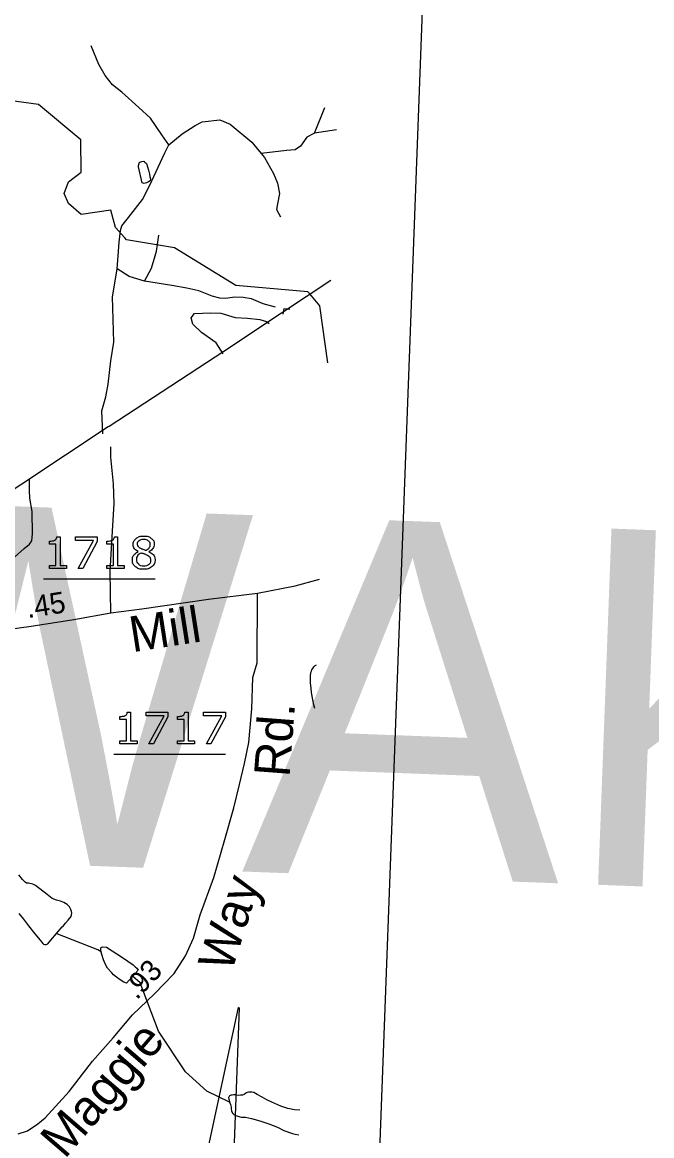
# Model space of a CAD drawing. Extents: x 2169602 to 2449496, y 721995 to 810662.
# Drawn here: x 2170523.6 to 2170611.8, y 724801.1 to 724957.3 of the extents above; entities that cross this region are included whole.
import ezdxf

# ---------------------------------------------------------------- set-up
doc = ezdxf.new("R2010")
doc.units = 0
for name, color, linetype in [('Old_Level_1', 7, 'Continuous'), ('Prop North Arrow NAD83 for Plan Sheets CELL', 7, 'Continuous'), ('Sheet Data Field CELL', 7, 'Continuous')]:
    doc.layers.add(name, color=color, linetype=linetype)

msp = doc.modelspace()

# ---------------------------------------------------------------- linework, layer by layer
at = {"layer": 'Old_Level_1'}
for p, q in [((2170564.57, 724941.75), (2170566.01, 724945.36)), ((2170542.53, 724926.15), (2170542.74, 724927.43)), ((2170544.93, 724925.69), (2170543.23, 724925.97)), ((2170536.87, 724922.74), (2170537.02, 724924.53)), ((2170526.53, 724879.25), (2170542.18, 724879.25)), ((2170536.42, 724854.66), (2170552.05, 724854.66))]:
    msp.add_line(p, q, dxfattribs=at)
msp.add_lwpolyline([(2170008.61, 724987.87), (2170579.91, 724966.5), (2170563.13, 724517.9), (2169991.83, 724539.28)], close=True, dxfattribs=at)
for points in [[(2170544.11, 724940.14), (2170543.16, 724941.52), (2170541.53, 724943.87), (2170539.9, 724945.35), (2170537.51, 724947.51), (2170536.22, 724948.56), (2170535.19, 724949.86), (2170534.28, 724951.39), (2170533.24, 724954.03)], [(2170537.96, 724927.07), (2170536.62, 724928.54), (2170536, 724930.97), (2170531.84, 724930.35), (2170530.06, 724931.87), (2170529.46, 724933.29), (2170530.03, 724934.91), (2170531.81, 724936.28), (2170531.79, 724940.8), (2170525.83, 724945.76), (2170519.29, 724946.67), (2170511.16, 724948.86)], [(2170544.11, 724940.14), (2170545.98, 724941.67), (2170547.8, 724942.82), (2170548.8, 724943.34), (2170551.29, 724943.63), (2170552.73, 724943.04), (2170555.75, 724940.51), (2170557.08, 724938.92)], [(2170567.63, 724942.23), (2170564.57, 724941.75)], [(2170564.57, 724941.75), (2170563.49, 724941.21), (2170562.59, 724939.95), (2170561.86, 724939.41), (2170560.6, 724939.32), (2170557.08, 724938.92)], [(2170537.26, 724927.25), (2170537.35, 724928.09), (2170537.53, 724928.76), (2170538.48, 724929.94), (2170540.41, 724932.46), (2170541.41, 724934.36), (2170543.57, 724939.01), (2170544.11, 724940.14)], [(2170557.08, 724938.92), (2170557.56, 724938.35), (2170558.78, 724936.09), (2170559.36, 724934.74), (2170559.63, 724933.29), (2170559.36, 724931.85), (2170559.23, 724931.04), (2170559.77, 724930.04)], [(2170540.39, 724934.81), (2170539.85, 724937.04), (2170539.85, 724937.22), (2170539.91, 724937.37), (2170539.95, 724937.52), (2170539.98, 724937.61), (2170540.04, 724937.71), (2170540.32, 724937.8), (2170540.6, 724937.81), (2170540.75, 724937.71), (2170540.99, 724937.48), (2170541.13, 724937.05), (2170541.28, 724936.58), (2170541.43, 724936), (2170541.47, 724935.67), (2170541.53, 724935.34), (2170541.48, 724935.05), (2170541.29, 724934.91), (2170541.01, 724934.77), (2170540.68, 724934.72), (2170540.39, 724934.81)], [(2170537.02, 724924.53), (2170537.17, 724926.46), (2170537.26, 724927.25)], [(2170543.23, 724925.97), (2170538.2, 724926.79), (2170537.96, 724927.07)], [(2170542.19, 724924.57), (2170542.38, 724925.22), (2170542.53, 724926.15)], [(2170563.91, 724919.2), (2170563.63, 724919.49), (2170553.51, 724920.4), (2170544.93, 724925.69)], [(2170540.71, 724921.02), (2170541.7, 724922.83), (2170542.19, 724924.57)], [(2170534.87, 724899.58), (2170534.73, 724902.79), (2170535.27, 724904.76), (2170535.63, 724906.56), (2170535.97, 724909.83), (2170536.39, 724912.45), (2170536.21, 724918.81), (2170536.53, 724920.71), (2170536.87, 724922.74)], [(2170540.71, 724921.02), (2170538.54, 724921.66), (2170536.87, 724922.74)], [(2170417.23, 724821.97), (2170433.34, 724832.72), (2170448.5, 724842.85), (2170457.43, 724848.85), (2170467.79, 724855.75), (2170474.14, 724859.99), (2170498.15, 724875.69), (2170499.4, 724876.6), (2170535.62, 724900.59), (2170535.75, 724900.68), (2170551.83, 724911.18), (2170559.94, 724916.55), (2170566.84, 724921.16)], [(2170417.23, 724821.97), (2170433.34, 724832.72), (2170448.5, 724842.85), (2170457.43, 724848.84), (2170467.79, 724855.75), (2170474.14, 724859.99), (2170498.15, 724875.69), (2170499.4, 724876.6), (2170535.62, 724900.59), (2170535.75, 724900.67), (2170551.83, 724911.18), (2170559.94, 724916.55), (2170566.84, 724921.16)], [(2170559.06, 724917.37), (2170557.35, 724917.82), (2170555.73, 724918.5), (2170554.55, 724918.72), (2170553.38, 724918.77), (2170552.07, 724918.59), (2170551.26, 724918.63), (2170550.22, 724918.9), (2170548.33, 724919.63), (2170546.66, 724920.03), (2170544.54, 724920.39), (2170540.71, 724921.02)], [(2170565.3, 724917.52), (2170563.91, 724919.2)], [(2170561.11, 724917.02), (2170560.26, 724917.14), (2170560.12, 724916.36)], [(2170566.4, 724909.52), (2170565.3, 724917.52)], [(2170551.75, 724910.8), (2170550.77, 724912.33), (2170548.69, 724913.78), (2170547.48, 724914.95), (2170547.25, 724915.85), (2170547.7, 724916.44), (2170549.96, 724916.57), (2170551.4, 724916.53), (2170553.43, 724915.9), (2170555.14, 724915.81), (2170556.9, 724915.63), (2170557.81, 724915.36), (2170558.17, 724915.06)], [(2170536, 724874.47), (2170535.91, 724880.28), (2170536.21, 724885.91), (2170536.47, 724889.8), (2170536.34, 724892.57), (2170536, 724896.33), (2170536, 724897.78)], [(2170519.01, 724871.83), (2170519.14, 724874.22), (2170520.08, 724878.27), (2170520.67, 724879.9), (2170521.44, 724881.13), (2170522.47, 724882.29), (2170523.83, 724883.48), (2170524.6, 724884.12), (2170524.9, 724884.59), (2170524.98, 724885.57), (2170524.94, 724888.69), (2170524.64, 724890.57), (2170524.6, 724891.63), (2170524.6, 724893.29)], [(2170529.77, 724880.68), (2170527.36, 724880.68), (2170527.36, 724881.13), (2170528.29, 724881.13), (2170528.29, 724884.12), (2170527.36, 724884.12), (2170527.36, 724884.53)], [(2170528.4, 724885.15), (2170528.87, 724885.15), (2170528.87, 724881.13), (2170529.77, 724881.13), (2170529.77, 724880.68)], [(2170534.08, 724884.47), (2170532.07, 724880.68), (2170531.42, 724880.68), (2170533.56, 724884.61), (2170531.03, 724884.61), (2170531.03, 724885.13), (2170534.08, 724885.13), (2170534.08, 724884.47)], [(2170537.85, 724880.68), (2170535.44, 724880.68), (2170535.44, 724881.13), (2170536.37, 724881.13), (2170536.37, 724884.12), (2170535.44, 724884.12), (2170535.44, 724884.53)], [(2170536.48, 724885.15), (2170536.94, 724885.15), (2170536.94, 724881.13), (2170537.85, 724881.13), (2170537.85, 724880.68)], [(2170539.83, 724883.06), (2170539.83, 724883.08)], [(2170541.31, 724883.05), (2170541.31, 724883.03)], [(2170556.57, 724877.25), (2170561.82, 724878.28), (2170565.27, 724879.21)], [(2170500.4, 724868.76), (2170503.57, 724869.12), (2170505.9, 724869.51), (2170512.65, 724870.76), (2170519.01, 724871.83), (2170524.83, 724872.61), (2170530.81, 724873.53), (2170536, 724874.47), (2170540.31, 724875.06), (2170549.66, 724876.38), (2170556.57, 724877.25)], [(2170522.98, 724801.38), (2170524.28, 724801.8), (2170525.74, 724802.82), (2170526.77, 724803.63), (2170530.12, 724807.35), (2170533.41, 724811.59), (2170536.33, 724814.88), (2170539.03, 724818.09), (2170542.1, 724821.02), (2170543.42, 724822.41), (2170544.88, 724823.87), (2170546.48, 724826.35), (2170547.58, 724828.84), (2170548.53, 724832.12), (2170550.41, 724837.35), (2170551.99, 724842.68), (2170553.23, 724847.12), (2170554.05, 724850.38), (2170554.73, 724853.32), (2170555.32, 724856.28), (2170555.76, 724861), (2170555.88, 724865.41), (2170556.53, 724867.47), (2170556.57, 724877.25)], [(2170564.59, 724861.07), (2170564.46, 724861.56), (2170564.31, 724862.27), (2170564.15, 724863.32), (2170564.06, 724863.89), (2170564.01, 724864.6), (2170564, 724865.07), (2170564, 724865.59), (2170564.05, 724866.12), (2170564.14, 724866.31), (2170564.19, 724866.5), (2170564.33, 724866.69), (2170564.47, 724866.88), (2170564.66, 724867.07), (2170564.82, 724867.2)], [(2170539.67, 724856.09), (2170537.26, 724856.09), (2170537.26, 724856.54), (2170538.18, 724856.54), (2170538.18, 724859.53), (2170537.26, 724859.53), (2170537.26, 724859.94)], [(2170538.29, 724860.56), (2170538.76, 724860.56), (2170538.76, 724856.54), (2170539.67, 724856.54), (2170539.67, 724856.09)], [(2170543.97, 724859.88), (2170541.96, 724856.09), (2170541.32, 724856.09), (2170543.45, 724860.02), (2170540.92, 724860.02), (2170540.92, 724860.54), (2170543.97, 724860.54), (2170543.97, 724859.88)], [(2170547.74, 724856.09), (2170545.33, 724856.09), (2170545.33, 724856.54), (2170546.26, 724856.54), (2170546.26, 724859.53), (2170545.33, 724859.53), (2170545.33, 724859.94)], [(2170546.37, 724860.56), (2170546.83, 724860.56), (2170546.83, 724856.54), (2170547.74, 724856.54), (2170547.74, 724856.09)], [(2170552.05, 724859.88), (2170550.03, 724856.09), (2170549.39, 724856.09), (2170551.53, 724860.02), (2170549, 724860.02), (2170549, 724860.54), (2170552.05, 724860.54), (2170552.05, 724859.88)], [(2170529.28, 724830.53), (2170529.61, 724830.96), (2170529.98, 724831.38), (2170530.42, 724831.86), (2170530.5, 724832.34), (2170530.46, 724832.58), (2170530.36, 724832.86), (2170530.17, 724833.24), (2170529.87, 724833.57), (2170529.39, 724833.85), (2170528.93, 724834.04), (2170528.36, 724834.18), (2170527.78, 724834.42), (2170527.06, 724834.98), (2170525.44, 724836.21), (2170525.06, 724836.4), (2170524.45, 724836.54), (2170524.16, 724836.58), (2170523.97, 724836.72), (2170523.58, 724837.05), (2170523.06, 724837.71)], [(2170523.1, 724832.3), (2170523.72, 724831.49), (2170524.43, 724830.59), (2170525.33, 724829.46), (2170526.06, 724828.56), (2170526.45, 724828.09), (2170526.54, 724827.99), (2170526.72, 724827.94), (2170526.92, 724827.95), (2170527.15, 724828.04), (2170527.58, 724828.57), (2170528.38, 724829.52), (2170529.18, 724830.44), (2170529.28, 724830.53)], [(2170534.61, 724826.91), (2170534.18, 724827.19), (2170528.34, 724829.48)], [(2170538.96, 724823.41), (2170538.16, 724822.54), (2170537.83, 724822.69), (2170537.31, 724823.02), (2170536.78, 724823.35), (2170536.34, 724823.72), (2170536.11, 724823.96), (2170535.53, 724824.63), (2170535.25, 724825.14), (2170534.95, 724825.8), (2170534.72, 724826.57), (2170534.62, 724826.9), (2170534.56, 724827.18), (2170534.56, 724827.42), (2170534.62, 724827.51), (2170534.71, 724827.57)], [(2170534.71, 724827.57), (2170534.86, 724827.61), (2170535.38, 724827.57), (2170537.61, 724826.15), (2170539.1, 724825.12), (2170539.39, 724824.83), (2170539.62, 724824.65), (2170539.8, 724824.37), (2170538.96, 724823.41)], [(2170552.65, 724805.86), (2170549.47, 724807.37), (2170546.47, 724810.09), (2170542.69, 724815.78), (2170540.1, 724822.59), (2170539.03, 724823.49)], [(2170552.64, 724806.71), (2170552.55, 724806.56), (2170552.5, 724806.47), (2170552.55, 724806.28), (2170552.56, 724806.14), (2170552.69, 724805.76), (2170552.79, 724805.53), (2170552.84, 724805.14), (2170552.84, 724804.91), (2170552.89, 724804.62), (2170553.03, 724804.29), (2170553.22, 724804.1), (2170553.52, 724803.96), (2170554.09, 724803.78), (2170554.33, 724803.73), (2170554.85, 724803.73), (2170555.71, 724803.54), (2170556.89, 724803.22), (2170558.13, 724802.8), (2170559.36, 724802.33), (2170560.27, 724801.86), (2170561.47, 724801.44), (2170561.85, 724801.35), (2170562.35, 724801.26)], [(2170562.48, 724804.73), (2170561.73, 724804.77), (2170560.82, 724804.96), (2170559.83, 724805.28), (2170558.58, 724805.84), (2170557.87, 724806.17), (2170557.21, 724806.54), (2170556.49, 724806.92), (2170556.02, 724807.21), (2170555.77, 724807.25), (2170555.29, 724807.25), (2170555.11, 724807.2), (2170554.93, 724807.1), (2170554.69, 724806.92), (2170554.45, 724806.82), (2170554.16, 724806.81), (2170553.92, 724806.77), (2170553.55, 724806.81), (2170553.4, 724806.86), (2170553.17, 724806.86), (2170553.02, 724806.81), (2170552.84, 724806.81), (2170552.74, 724806.76), (2170552.64, 724806.71)]]:
    msp.add_lwpolyline(points, dxfattribs=at)
for points in [[(2170527.36, 724884.53), (2170527.55, 724884.53), (2170527.77, 724884.56), (2170527.98, 724884.59), (2170528.09, 724884.65), (2170528.23, 724884.72), (2170528.31, 724884.84), (2170528.39, 724884.95), (2170528.4, 724885.15)], [(2170535.44, 724884.53), (2170535.63, 724884.53), (2170535.84, 724884.56), (2170536.06, 724884.59), (2170536.17, 724884.65), (2170536.31, 724884.72), (2170536.39, 724884.84), (2170536.47, 724884.95), (2170536.48, 724885.15)], [(2170539.83, 724883.08), (2170539.47, 724883.27), (2170539.3, 724883.49), (2170539.13, 724883.72), (2170539.13, 724884.06), (2170539.13, 724884.57), (2170539.54, 724884.9), (2170539.96, 724885.24), (2170540.59, 724885.24), (2170541.26, 724885.24), (2170541.66, 724884.92), (2170542.06, 724884.6), (2170542.06, 724884.1), (2170542.06, 724883.8), (2170541.87, 724883.51), (2170541.68, 724883.22), (2170541.31, 724883.05)], [(2170541.47, 724884.1), (2170541.47, 724884.42), (2170541.22, 724884.61), (2170540.97, 724884.8), (2170540.59, 724884.8), (2170540.21, 724884.8), (2170539.97, 724884.62), (2170539.73, 724884.44), (2170539.73, 724884.13), (2170539.73, 724883.92), (2170539.85, 724883.76), (2170539.97, 724883.6), (2170540.22, 724883.48), (2170540.33, 724883.43), (2170540.54, 724883.34), (2170540.75, 724883.25), (2170540.94, 724883.2), (2170541.24, 724883.39), (2170541.35, 724883.61), (2170541.47, 724883.82), (2170541.47, 724884.1)], [(2170542.18, 724881.92), (2170542.18, 724881.34), (2170541.73, 724880.96), (2170541.28, 724880.58), (2170540.59, 724880.58), (2170539.87, 724880.58), (2170539.44, 724880.95), (2170539.01, 724881.32), (2170539.01, 724881.91), (2170539.01, 724882.28), (2170539.22, 724882.58), (2170539.44, 724882.88), (2170539.83, 724883.06)], [(2170541.56, 724881.86), (2170541.56, 724882.14), (2170541.44, 724882.31), (2170541.32, 724882.47), (2170540.97, 724882.64), (2170540.83, 724882.7), (2170540.66, 724882.76), (2170540.49, 724882.82), (2170540.21, 724882.92), (2170539.94, 724882.77), (2170539.78, 724882.52), (2170539.62, 724882.27), (2170539.62, 724881.95), (2170539.62, 724881.55), (2170539.9, 724881.29), (2170540.17, 724881.02), (2170540.6, 724881.02), (2170541.04, 724881.02), (2170541.3, 724881.25), (2170541.56, 724881.47), (2170541.56, 724881.86)], [(2170541.31, 724883.03), (2170541.73, 724882.85), (2170541.96, 724882.59), (2170542.18, 724882.33), (2170542.18, 724881.92)], [(2170537.26, 724859.94), (2170537.44, 724859.94), (2170537.66, 724859.97), (2170537.87, 724860), (2170537.99, 724860.06), (2170538.12, 724860.13), (2170538.2, 724860.25), (2170538.28, 724860.36), (2170538.29, 724860.56)], [(2170545.33, 724859.94), (2170545.52, 724859.94), (2170545.74, 724859.97), (2170545.95, 724860), (2170546.06, 724860.06), (2170546.2, 724860.13), (2170546.28, 724860.25), (2170546.36, 724860.36), (2170546.37, 724860.56)]]:
    msp.add_open_spline(points, degree=3, dxfattribs=at)
at = {"layer": 'Prop North Arrow NAD83 for Plan Sheets CELL'}
for p, q in [((2170539.01, 724750.08), (2170553.91, 724819.1)), ((2170553.98, 724819.09), (2170551.3, 724747.44)), ((2170553.98, 724819.09), (2170553.91, 724819.1)), ((2170553.98, 724819.09), (2170553.91, 724819.1))]:
    msp.add_line(p, q, dxfattribs=at)

# ---------------------------------------------------------------- texts
at = {"layer": 'Old_Level_1'}
for s, height, rotation, p in [('.45', 2.971, 8.7706, (2170524.34, 724873.72)), ('Mill', 5, 8.8746, (2170538.99, 724868.94)), ('Rd.', 5, 85.6487, (2170561.04, 724851.35)), ('Way', 5, 72.3982, (2170552.9, 724823.89)), ('.93', 2.971, 46.5662, (2170539.61, 724820.09)), ('Maggie', 5, 49.3335, (2170529.51, 724797.75))]:
    msp.add_text(s, height=height, rotation=rotation, dxfattribs=at).set_placement(p)
at = {"layer": 'Sheet Data Field CELL'}
msp.add_text('         WAKE COUNTY         ', height=50, rotation=357.8574, dxfattribs=at).set_placement((2170324.15, 724846.81))

doc.saveas('drawing.dxf')
